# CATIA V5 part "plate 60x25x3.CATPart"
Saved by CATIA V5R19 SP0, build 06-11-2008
Part number: plate 60x25x3
Bounding box of the stored display mesh (mm): x -60 to 0, y 0 to 3, z 0 to 25
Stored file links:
  D:\AUTO BATCH (BHEL)\Collecting Hopper 2\plate 60x25x3.CATPart
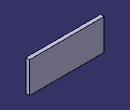
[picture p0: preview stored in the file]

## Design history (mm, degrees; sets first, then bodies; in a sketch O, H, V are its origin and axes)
SheetMetalParameters1: BendRadius 3, ReliefAxialLength 2, ReliefRadialLength 1, MinimumBendRadius 0, Thickness 3, KFactor 0.325257 {= log(min(100,max(20*SheetMetalParameters1.BendRadius,SheetMetalParameters1.Thickness)/SheetMetalParameters1.Thickness))/log(100)/2}
Set1
  Sketch1 on zx-plane, origin (0, 0, 0), H (-1, 0, 0), V (0, 0, 1)
    line L1 (0, 0) -> (60, 0)
    line L2 (60, 0) -> (60, 25)
    line L3 (60, 25) -> (0, 25)
    line L4 (0, 25) -> (0, 0)
    length L1 = 60
    length L2 = 25
    horizontal: L1 H, L3 H
    vertical: L2 V, L4 V
Body1 (main body)
  Wall1: Thickness 3, Profile Sketch1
